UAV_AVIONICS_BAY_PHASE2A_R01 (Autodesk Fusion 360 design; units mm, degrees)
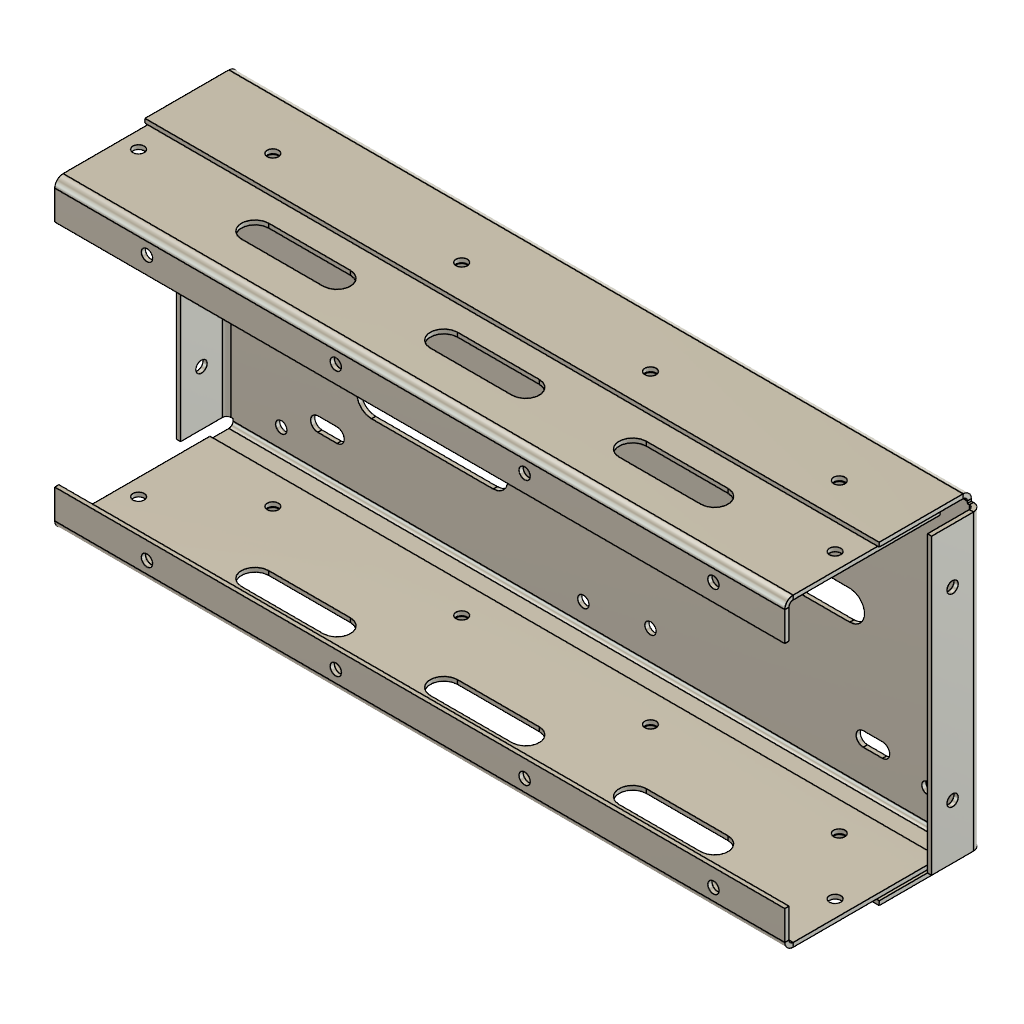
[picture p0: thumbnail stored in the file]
part number: 2026-11-23-23-26-55-607
part number: 2026-11-23-23-26-55-805
part number: 2026-11-23-23-26-55-815
part number: 2026-11-23-23-26-55-830
part number: 2026-11-23-23-26-55-838
part number: 2026-11-23-23-26-55-850
part number: 2026-11-23-23-26-55-859
part number: 2026-11-23-23-26-55-870
part number: 2026-11-23-23-26-55-880
part number: 2026-11-23-23-26-55-924
part number: 2026-11-23-23-26-56-778
part number: 2026-11-23-23-26-57-220
parameter "BAY_LENGTH" = 180 comment "[Assumption] Concept avionics bay overall outer length (X)"
parameter "BAY_WIDTH" = 75 comment "[Assumption] Concept avionics bay overall outer width (Y)"
parameter "BAY_HEIGHT" = 45 comment "[Assumption] Concept avionics bay overall outer height (Z)"
parameter "TRAY_FLANGE_H" = 22 comment "[Preliminary] Base tray perimeter upward flange height"
parameter "COVER_SKIRT_H" = 10 comment "[Preliminary] Top cover downward perimeter skirt height"
parameter "FORWARD_ZONE_END_X" = 95 comment "[Preliminary] X-boundary separating battery zone and aft deck"
parameter "HATCH_LENGTH" = 92 comment "[Preliminary] Service access hatch opening length"
parameter "HATCH_WIDTH" = 54 comment "[Preliminary] Service access hatch opening width"
parameter "T_BASE_TRAY" = 1 comment "[Preliminary] Main folded base tray thickness"
parameter "T_TOP_COVER" = 0.8 comment "[Preliminary] Removable top cover thickness"
parameter "T_ACCESS_HATCH" = 0.8 comment "[Preliminary] Service access hatch thickness"
parameter "T_SIDE_RAIL" = 1 comment "[Preliminary] Left and right side support rails thickness"
parameter "T_BULKHEAD" = 1 comment "[Preliminary] Front, rear, and connector bulkheads thickness"
parameter "T_EQUIP_DECK" = 1 comment "[Preliminary] Removable internal equipment deck thickness"
parameter "T_BRACKET" = 1 comment "[Preliminary] Structural and retention brackets thickness"
parameter "T_CABLE_CH" = 0.8 comment "[Preliminary] Cable routing channel and clamp thickness"
parameter "BEND_R_1_0" = 1 comment "[Preliminary] Inside bend radius for 1.0 mm Al 5052-H32"
parameter "BEND_R_0_8" = 0.8 comment "[Preliminary] Inside bend radius for 0.8 mm Al 5052-H32"
parameter "RELIEF_W_1_0" = 1.5 comment "[Preliminary] Bend relief width for 1.0 mm sheet"
parameter "RELIEF_D_1_0" = 2.5 comment "[Preliminary] Bend relief depth for 1.0 mm sheet"
parameter "RELIEF_W_0_8" = 1.2 comment "[Preliminary] Bend relief width for 0.8 mm sheet"
parameter "RELIEF_D_0_8" = 2.1 comment "[Preliminary] Bend relief depth for 0.8 mm sheet"
parameter "HOLE_CLR_M2_0" = 2.2 comment "[Preliminary] M2.0 medium clearance hole diameter"
parameter "HOLE_CLR_M2_5" = 2.7 comment "[Preliminary] M2.5 medium clearance hole diameter"
parameter "HOLE_CLR_M3_0" = 3.4 comment "[Preliminary] M3.0 medium clearance hole diameter"
parameter "HEAD_DIA_M2_0" = 3.8 comment "[Preliminary] ISO 4762/7380 M2.0 head diameter"
parameter "HEAD_DIA_M2_5" = 4.5 comment "[Preliminary] ISO 4762/7380 M2.5 head diameter"
parameter "STANDOFF_DECK_H" = 6 comment "[Preliminary] Under-deck plenum standoff height"
parameter "STANDOFF_PCB_H" = 4 comment "[Preliminary] PCB mounting standoff height"
parameter "ISO_PAD_THICK" = 2 comment "[Preliminary] Battery elastomer isolation pad thickness"
parameter "CLR_EQUIP_WALL" = 2 comment "[Preliminary] Minimum clearance between electronics and walls"
parameter "CLR_COMPONENT" = 1.5 comment "[Preliminary] General minimum clearance between adjacent parts"
parameter "CLR_SLIP_FIT" = 0.25 comment "[Preliminary] Per-side slip clearance for nested sheet metal parts"
parameter "CLR_COVER_FIT" = 0.3 comment "[Preliminary] Per-side clearance between cover skirt and chassis"
parameter "CLR_HATCH_GAP" = 0.5 comment "[Preliminary] Perimeter gap around removable service hatch"
parameter "d37" = 2
parameter "d38" = 1
parameter "d39" = 0.8
sketch "SK_Base_Tray_Blank" plane through (0, 0, 0) normal (0, 0, 1) x axis (1, 0, 0)
  line L1 (177.5, -37.5) -> (2.5, -37.5)
  line L2 (177.5, -35) -> (177.5, -37.5)
  line L3 (180, -35) -> (177.5, -35)
  line L4 (180, 35) -> (180, -35)
  line L5 (177.5, 35) -> (180, 35)
  line L6 (177.5, 37.5) -> (177.5, 35)
  line L7 (2.5, 37.5) -> (177.5, 37.5)
  line L8 (2.5, 35) -> (2.5, 37.5)
  line L9 (0, 35) -> (2.5, 35)
  line L10 (0, -35) -> (0, 35)
  line L11 (2.5, -35) -> (0, -35)
  line L12 (2.5, -37.5) -> (2.5, -35)
face "BaseFlange1" sketch "SK_Base_Tray_Blank"
face "EdgeFlange2" FlangeHeight 22 FlangeAngle 90
face "EdgeFlange3" FlangeHeight 12 FlangeAngle 90
sketch "SK_Base_Tray_Floor_Cutouts" plane through (0, 0, 0) normal (0, 0, 1) x axis (1, 0, 0)
  line L1 (27.3, -24.3) -> (22.7, -24.3)
  line L2 (22.7, -27.7) -> (27.3, -27.7)
  line L3 (27.3, 27.7) -> (22.7, 27.7)
  line L4 (22.7, 24.3) -> (27.3, 24.3)
  line L5 (157.3, -24.3) -> (152.7, -24.3)
  line L6 (152.7, -27.7) -> (157.3, -27.7)
  line L7 (157.3, 27.7) -> (152.7, 27.7)
  line L8 (152.7, 24.3) -> (157.3, 24.3)
  line L9 (64.5, -11.5) -> (35.5, -11.5)
  line L10 (35.5, -18.5) -> (64.5, -18.5)
  line L11 (149.5, 3.5) -> (120.5, 3.5)
  line L12 (120.5, -3.5) -> (149.5, -3.5)
  arc A1 centre (27.3, -26) radius 1.7 clockwise from (27.3, -24.3) to (27.3, -27.7)
  arc A2 centre (22.7, -26) radius 1.7 clockwise from (22.7, -27.7) to (22.7, -24.3)
  arc A3 centre (27.3, 26) radius 1.7 clockwise from (27.3, 27.7) to (27.3, 24.3)
  arc A4 centre (22.7, 26) radius 1.7 clockwise from (22.7, 24.3) to (22.7, 27.7)
  arc A5 centre (157.3, -26) radius 1.7 clockwise from (157.3, -24.3) to (157.3, -27.7)
  arc A6 centre (152.7, -26) radius 1.7 clockwise from (152.7, -27.7) to (152.7, -24.3)
  arc A7 centre (157.3, 26) radius 1.7 clockwise from (157.3, 27.7) to (157.3, 24.3)
  arc A8 centre (152.7, 26) radius 1.7 clockwise from (152.7, 24.3) to (152.7, 27.7)
  circle C1 centre (102, -28.5) radius 1.35
  circle C2 centre (102, 28.5) radius 1.35
  circle C3 centre (168, -28.5) radius 1.35
  circle C4 centre (168, 28.5) radius 1.35
  circle C5 centre (14, -31) radius 1.35
  circle C6 centre (14, 1) radius 1.35
  circle C7 centre (86, -31) radius 1.35
  circle C8 centre (86, 1) radius 1.35
  circle C9 centre (13, 11) radius 1.1
  circle C10 centre (13, 27) radius 1.1
  circle C11 centre (45, 11) radius 1.1
  circle C12 centre (45, 27) radius 1.1
  circle C13 centre (57, 11) radius 1.1
  circle C14 centre (57, 27) radius 1.1
  circle C15 centre (85, 11) radius 1.1
  circle C16 centre (85, 27) radius 1.1
  arc A9 centre (64.5, -15) radius 3.5 clockwise from (64.5, -11.5) to (64.5, -18.5)
  arc A10 centre (35.5, -15) radius 3.5 clockwise from (35.5, -18.5) to (35.5, -11.5)
  arc A11 centre (149.5, 0) radius 3.5 clockwise from (149.5, 3.5) to (149.5, -3.5)
  arc A12 centre (120.5, 0) radius 3.5 clockwise from (120.5, -3.5) to (120.5, 3.5)
extrude "Extrude1" cut sketch "SK_Base_Tray_Floor_Cutouts" distance 2
work_plane "WorkPlane1" AlongDistance -37.5 ExtraOffset 0
sketch "SK_Tray_Left_Wall_Holes" plane through (0, -37.5, 0) normal (0, 1, 0) x axis (1, 0, 0)
  circle C1 centre (25, -14) radius 1.35
  circle C2 centre (70, -14) radius 1.35
  circle C3 centre (115, -14) radius 1.35
  circle C4 centre (160, -14) radius 1.35
extrude "Extrude2" cut sketch "SK_Tray_Left_Wall_Holes" distance 2
work_plane "WorkPlane2" AlongDistance 37.5 ExtraOffset 0
sketch "SK_Tray_Right_Wall_Holes" plane through (0, 37.5, 0) normal (0, 1, 0) x axis (1, 0, 0)
  circle C1 centre (25, -14) radius 1.35
  circle C2 centre (70, -14) radius 1.35
  circle C3 centre (115, -14) radius 1.35
  circle C4 centre (160, -14) radius 1.35
extrude "Extrude3" cut sketch "SK_Tray_Right_Wall_Holes" distance 2
sketch "SK_Tray_Front_Lip_Holes" plane through (0, 0, 0) normal (1, 0, 0) x axis (0, 0, -1)
  circle C1 centre (-7, -22) radius 1.35
  circle C2 centre (-7, 22) radius 1.35
extrude "Extrude4" cut sketch "SK_Tray_Front_Lip_Holes" distance 2
work_plane "WorkPlane3" AlongDistance 180 ExtraOffset 0
sketch "SK_Tray_Rear_Lip_Holes" plane through (180, 0, 0) normal (1, 0, 0) x axis (0, 0, -1)
  circle C1 centre (-7, -22) radius 1.35
  circle C2 centre (-7, 22) radius 1.35
extrude "Extrude5" cut sketch "SK_Tray_Rear_Lip_Holes" distance 2
work_plane "WorkPlane1" AlongDistance -36.35 ExtraOffset 0
sketch "SK_PDB-01-102_Left_Side_Rail_Web" plane through (0, -36.35, 0) normal (0, 1, 0) x axis (1, 0, 0)
  line L1 (177, -7) -> (3, -7)
  line L2 (177, -44) -> (177, -7)
  line L3 (3, -44) -> (177, -44)
  line L4 (3, -7) -> (3, -44)
face "BaseFlange1" sketch "SK_PDB-01-102_Left_Side_Rail_Web"
face "EdgeFlange2" FlangeHeight 9 FlangeAngle 90
sketch "SK_PDB-01-102_Left_Side_Rail_Web_Features" plane through (0, -36.35, 0) normal (0, 1, 0) x axis (1, 0, 0)
  line L1 (57.25, -34.25) -> (37.75, -34.25)
  line L2 (37.75, -27.75) -> (57.25, -27.75)
  line L3 (102.25, -34.25) -> (82.75, -34.25)
  line L4 (82.75, -27.75) -> (102.25, -27.75)
  line L5 (147.25, -34.25) -> (127.75, -34.25)
  line L6 (127.75, -27.75) -> (147.25, -27.75)
  circle C1 centre (25, -14) radius 1.35
  circle C2 centre (70, -14) radius 1.35
  circle C3 centre (115, -14) radius 1.35
  circle C4 centre (160, -14) radius 1.35
  circle C5 centre (7, -28) radius 1.35
  circle C6 centre (173, -28) radius 1.35
  arc A1 centre (57.25, -31) radius 3.25 clockwise from (57.25, -27.75) to (57.25, -34.25)
  arc A2 centre (37.75, -31) radius 3.25 clockwise from (37.75, -34.25) to (37.75, -27.75)
  arc A3 centre (102.25, -31) radius 3.25 clockwise from (102.25, -27.75) to (102.25, -34.25)
  arc A4 centre (82.75, -31) radius 3.25 clockwise from (82.75, -34.25) to (82.75, -27.75)
  arc A5 centre (147.25, -31) radius 3.25 clockwise from (147.25, -27.75) to (147.25, -34.25)
  arc A6 centre (127.75, -31) radius 3.25 clockwise from (127.75, -34.25) to (127.75, -27.75)
extrude "Extrude1" cut sketch "SK_PDB-01-102_Left_Side_Rail_Web_Features" distance 2
work_plane "WorkPlane2" AlongDistance 44 ExtraOffset 0
sketch "SK_PDB-01-102_Left_Side_Rail_Top_Holes" plane through (0, 0, 44) normal (0, 0, 1) x axis (1, 0, 0)
  circle C1 centre (25, -31.5) radius 1.35
  circle C2 centre (70, -31.5) radius 1.35
  circle C3 centre (115, -31.5) radius 1.35
  circle C4 centre (160, -31.5) radius 1.35
extrude "Extrude2" cut sketch "SK_PDB-01-102_Left_Side_Rail_Top_Holes" distance 2
work_plane "WorkPlane1" AlongDistance 36.35 ExtraOffset 0
sketch "SK_PDB-01-103_Right_Side_Rail_Web" plane through (0, 36.35, 0) normal (0, 1, 0) x axis (1, 0, 0)
  line L1 (177, -7) -> (3, -7)
  line L2 (177, -44) -> (177, -7)
  line L3 (3, -44) -> (177, -44)
  line L4 (3, -7) -> (3, -44)
face "BaseFlange2" sketch "SK_PDB-01-103_Right_Side_Rail_Web"
face "EdgeFlange3" FlangeHeight 9 FlangeAngle 90
sketch "SK_PDB-01-103_Right_Side_Rail_Web_Features" plane through (0, 36.35, 0) normal (0, 1, 0) x axis (1, 0, 0)
  line L1 (57.25, -34.25) -> (37.75, -34.25)
  line L2 (37.75, -27.75) -> (57.25, -27.75)
  line L3 (102.25, -34.25) -> (82.75, -34.25)
  line L4 (82.75, -27.75) -> (102.25, -27.75)
  line L5 (147.25, -34.25) -> (127.75, -34.25)
  line L6 (127.75, -27.75) -> (147.25, -27.75)
  circle C1 centre (25, -14) radius 1.35
  circle C2 centre (70, -14) radius 1.35
  circle C3 centre (115, -14) radius 1.35
  circle C4 centre (160, -14) radius 1.35
  circle C5 centre (7, -28) radius 1.35
  circle C6 centre (173, -28) radius 1.35
  arc A1 centre (57.25, -31) radius 3.25 clockwise from (57.25, -27.75) to (57.25, -34.25)
  arc A2 centre (37.75, -31) radius 3.25 clockwise from (37.75, -34.25) to (37.75, -27.75)
  arc A3 centre (102.25, -31) radius 3.25 clockwise from (102.25, -27.75) to (102.25, -34.25)
  arc A4 centre (82.75, -31) radius 3.25 clockwise from (82.75, -34.25) to (82.75, -27.75)
  arc A5 centre (147.25, -31) radius 3.25 clockwise from (147.25, -27.75) to (147.25, -34.25)
  arc A6 centre (127.75, -31) radius 3.25 clockwise from (127.75, -34.25) to (127.75, -27.75)
extrude "Extrude1" cut sketch "SK_PDB-01-103_Right_Side_Rail_Web_Features" distance 2
work_plane "WorkPlane2" AlongDistance 44 ExtraOffset 0
sketch "SK_PDB-01-103_Right_Side_Rail_Top_Holes" plane through (0, 0, 44) normal (0, 0, 1) x axis (1, 0, 0)
  circle C1 centre (25, 31.5) radius 1.35
  circle C2 centre (70, 31.5) radius 1.35
  circle C3 centre (115, 31.5) radius 1.35
  circle C4 centre (160, 31.5) radius 1.35
extrude "Extrude2" cut sketch "SK_PDB-01-103_Right_Side_Rail_Top_Holes" distance 2
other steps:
create_component "CreateComponent1"
create_component "CreateComponent2"
create_component "CreateComponent3"
create_component "CreateComponent4"
create_component "CreateComponent5"
create_component "CreateComponent6"
create_component "CreateComponent7"
create_component "CreateComponent8"
create_component "CreateComponent1"
create_component "CreateComponent2"
create_component "CreateComponent3"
